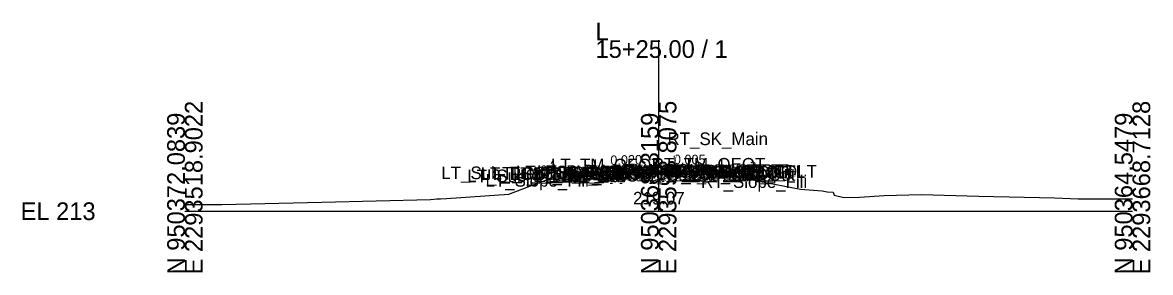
# Model space of a CAD drawing. Extents: x -26 to 7053, y -10 to 7035.
# Drawn here: x -25.7 to 152.8, y 6490.3 to 6529.9 of the extents above; entities that cross this region are included whole.
import ezdxf

# ---------------------------------------------------------------- set-up
doc = ezdxf.new("R2010")
doc.units = 0
for name, color, linetype in [('Default', 7, 'Continuous'), ('Exist Cross Section Cell', 7, 'Continuous'), ('Exist XS Center Line Elevation Label', 7, 'Continuous'), ('Exist XS Ground Line', 7, 'Continuous'), ('Prop CMT Pvmt Course 1', 7, 'Continuous'), ('Prop CMT Pvmt Course 2', 7, 'Continuous'), ('Prop CMT Pvmt Surface', 7, 'Continuous'), ('Prop CMT Pvmt Surface Overlay', 7, 'Continuous'), ('Prop CMT Pvmt Surface Shoulder', 7, 'Continuous'), ('Prop CMT Shld Paved Course 1', 7, 'Continuous'), ('Prop CMT Shld Paved Course 2', 7, 'Continuous'), ('Prop CMT Slope Grass', 7, 'Continuous'), ('Prop CMT Subgrade Earthwork', 7, 'Continuous'), ('Prop XS EOT Tick Mark', 7, 'Continuous'), ('Prop XS SE Text', 7, 'Continuous'), ('Prop XS Side Slope Text', 7, 'Continuous')]:
    doc.layers.add(name, color=color, linetype=linetype)

msp = doc.modelspace()

# ---------------------------------------------------------------- linework, layer by layer
at = {"layer": 'Exist Cross Section Cell'}
for p, q in [((75, 6500), (75, 6527.08)), ((0, 6500), (75, 6500)), ((75, 6500), (150, 6500))]:
    msp.add_line(p, q, dxfattribs=at)
at = {"layer": 'Exist XS Ground Line'}
for p, q in [((63.59, 6505.59), (66.19, 6505.83)), ((66.19, 6505.83), (68.01, 6505.89)), ((68.01, 6505.89), (74.91, 6506.07)), ((74.91, 6506.07), (80.13, 6505.93)), ((80.13, 6505.93), (83.17, 6505.86)), ((83.17, 6505.86), (85.02, 6505.7)), ((51.28, 6502.72), (56.42, 6504.65)), ((56.42, 6504.65), (57.47, 6505.04)), ((57.47, 6505.04), (63.59, 6505.59)), ((85.02, 6505.7), (87.85, 6505.45)), ((87.85, 6505.45), (90.85, 6504.76)), ((90.85, 6504.76), (97.44, 6503.49)), ((41.42, 6502.03), (51.28, 6502.72)), ((97.44, 6503.49), (100.87, 6503.21)), ((100.87, 6503.21), (101.69, 6503.07)), ((101.69, 6503.07), (102.61, 6503.02)), ((102.61, 6503.02), (102.8, 6502.54)), ((102.8, 6502.54), (104.29, 6502.15)), ((104.29, 6502.15), (106.81, 6502.24)), ((106.81, 6502.24), (110.69, 6502.49)), ((110.69, 6502.49), (116.57, 6502.63)), ((116.57, 6502.63), (125.67, 6502.41)), ((125.67, 6502.41), (137.64, 6502.11)), ((0, 6501.09), (0.37, 6501.08)), ((0.37, 6501.08), (1.81, 6501.09)), ((1.81, 6501.09), (5.83, 6501.05)), ((5.83, 6501.05), (21.68, 6501.42)), ((21.68, 6501.42), (38.87, 6501.87)), ((38.87, 6501.87), (39.9, 6501.97)), ((39.9, 6501.97), (40.48, 6501.96)), ((40.48, 6501.96), (41.42, 6502.03)), ((137.64, 6502.11), (141.39, 6501.97)), ((141.39, 6501.97), (150, 6501.95))]:
    msp.add_line(p, q, dxfattribs=at)
at = {"layer": 'Prop CMT Pvmt Course 1'}
for points in [[(75, 6506.47), (65, 6506.27)], [(65, 6506.27), (65, 6506.02)], [(65, 6506.02), (75, 6506.22)], [(75, 6506.35), (75, 6506.47)], [(75, 6506.47), (85, 6506.42)], [(75, 6506.35), (75, 6506.47)], [(75, 6506.22), (75, 6506.35), (75, 6506.35)], [(75, 6506.22), (75, 6506.35), (75, 6506.35)], [(85, 6506.17), (75, 6506.22)], [(85, 6506.42), (85, 6506.17)]]:
    msp.add_lwpolyline(points, dxfattribs=at)
at = {"layer": 'Prop CMT Pvmt Course 2'}
for points in [[(75, 6506.22), (65, 6506.02)], [(65, 6506.02), (65, 6505.69)], [(65, 6505.69), (75, 6505.89)], [(75, 6505.89), (75, 6506.22)], [(75, 6505.89), (75, 6506.22)], [(75, 6506.22), (85, 6506.17)], [(85, 6505.84), (75, 6505.89)], [(85, 6506.17), (85, 6505.84)]]:
    msp.add_lwpolyline(points, dxfattribs=at)
at = {"layer": 'Prop CMT Pvmt Surface'}
for points in [[(75, 6506.47), (65, 6506.27)], [(75, 6506.47), (85, 6506.42)]]:
    msp.add_lwpolyline(points, dxfattribs=at)
at = {"layer": 'Prop CMT Pvmt Surface Overlay'}
for points in [[(75, 6506.47), (65, 6506.27)], [(75, 6506.47), (85, 6506.42)]]:
    msp.add_lwpolyline(points, dxfattribs=at)
at = {"layer": 'Prop CMT Pvmt Surface Shoulder'}
for points in [[(65, 6506.27), (61.6, 6506.2)], [(85, 6506.42), (85.99, 6506.42)]]:
    msp.add_lwpolyline(points, dxfattribs=at)
at = {"layer": 'Prop CMT Shld Paved Course 1'}
for points in [[(65, 6506.27), (61.6, 6506.2), (61.34, 6505.95)], [(61.34, 6505.95), (65, 6506.02)], [(65, 6506.02), (65, 6506.27)], [(85, 6506.42), (85.99, 6506.42), (86.24, 6506.16)], [(85, 6506.17), (85, 6506.42)], [(86.24, 6506.16), (85, 6506.17)]]:
    msp.add_lwpolyline(points, dxfattribs=at)
at = {"layer": 'Prop CMT Shld Paved Course 2'}
for points in [[(65, 6506.02), (61.34, 6505.95), (60.84, 6505.94), (60.5, 6505.6)], [(65, 6505.69), (65, 6506.02)], [(85, 6506.17), (86.24, 6506.16), (86.74, 6506.16), (87.07, 6505.83)], [(85, 6505.84), (85, 6506.17)], [(87.07, 6505.83), (85, 6505.84)], [(60.5, 6505.6), (65, 6505.69)]]:
    msp.add_lwpolyline(points, dxfattribs=at)
at = {"layer": 'Prop CMT Slope Grass'}
for points in [[(59.33, 6506.02), (57.07, 6504.89)], [(61.6, 6506.2), (59.33, 6506.02)], [(85.99, 6506.42), (88.05, 6506.28)], [(88.05, 6506.28), (91.24, 6504.69)]]:
    msp.add_lwpolyline(points, dxfattribs=at)
at = {"layer": 'Prop CMT Subgrade Earthwork'}
for points in [[(60.5, 6505.6), (60.02, 6506.08)], [(75, 6505.89), (65, 6505.69)], [(75, 6505.89), (85, 6505.84)], [(85, 6505.84), (87.07, 6505.83)], [(87.07, 6505.83), (87.56, 6506.31)], [(65, 6505.69), (60.5, 6505.6)]]:
    msp.add_lwpolyline(points, dxfattribs=at)
at = {"layer": 'Prop XS EOT Tick Mark'}
for p, q in [((65, 6506.27), (65, 6508.18)), ((85, 6506.42), (85, 6508.33))]:
    msp.add_line(p, q, dxfattribs=at)

# ---------------------------------------------------------------- texts
at = {"layer": 'Default'}
for s, height, p in [('RT_SK_Main', 2, (76.4, 6510.47)), ('LT_TM_OEOT', 2, (57.94, 6506.31)), ('RT_TM_OEOT', 2, (73.9, 6506.43)), ('LT_Sub_Trench_Out_DLT', 2, (40.59, 6505.08)), ('LT_Sub_Trench_Out', 2, (44.7, 6504.6)), ('LT_PS2_Shelf_Out', 2, (46.82, 6504.94)), ('LT_Slope_Fill', 2, (47.59, 6503.89)), ('LT_GS_OS_CTL', 2, (48.7, 6505.02)), ('LT_PS2_OEOP', 2, (51.58, 6504.95)), ('LT_PS1_OEOP', 2, (52.4, 6505.2)), ('LT_Sub_OEOT', 2, (55.08, 6504.69)), ('LT_PV2_OEOT', 2, (55.17, 6505.02)), ('LT_PV1_OEOT', 2, (55.74, 6505.27)), ('RT_PV1_OEEOP_W', 2, (62.94, 6505.35)), ('LT_PV1_OEEOP_W', 2, (62.98, 6505.35)), ('RT_Sub_OEEOP', 2, (64.17, 6504.89)), ('LT_Sub_OEEOP', 2, (64.21, 6504.89)), ('RT_PV2_OEEOP', 2, (64.26, 6505.22)), ('LT_PV2_OEEOP', 2, (64.31, 6505.22)), ('PV1_PGL_W', 2, (67.58, 6505.35)), ('RT_Sub_Trench_Out_DLT', 2, (68.08, 6505.31)), ('PV1_PGL', 2, (69.47, 6505.47)), ('RT_Sub_Trench_Out', 2, (71.23, 6504.83)), ('RT_PS2_Shelf_Out', 2, (72.68, 6505.16)), ('RT_Sub_OEOT', 2, (75.03, 6504.84)), ('RT_PV2_OEOT', 2, (75.13, 6505.17)), ('RT_PV1_OEOT', 2, (75.69, 6505.42)), ('RT_PS2_OEOP', 2, (76.43, 6505.16)), ('RT_PS1_OEOP', 2, (76.74, 6505.42)), ('RT_GS_OS_CTL', 2, (77.37, 6505.28)), ('RT_Slope_Fill', 2, (81.71, 6503.69)), ('-', 0.0001, (0, 6500))]:
    msp.add_text(s, height=height, dxfattribs=at).set_placement(p)
at = {"layer": 'Exist Cross Section Cell'}
for s, p in [('L', (65, 6527.08)), ('15+25.00 / 1', (65, 6524.28)), ('EL 213', (-26, 6498.6))]:
    msp.add_text(s, height=2.8, dxfattribs=at).set_placement(p)
for s, p in [('E 2293518.9022', (2.8, 6490)), ('E 2293593.8075', (77.8, 6490)), ('E 2293668.7128', (152.8, 6490)), ('N 950372.0839', (0, 6490)), ('N 950368.3159', (75, 6490)), ('N 950364.5479', (150, 6490))]:
    msp.add_text(s, height=2.8, rotation=90, dxfattribs=at).set_placement(p)
at = {"layer": 'Exist XS Center Line Elevation Label'}
msp.add_text('219.07', height=2, dxfattribs=at).set_placement((70.94, 6501.07))
at = {"layer": 'Prop XS SE Text'}
for s, rotation, p in [('0.020', 1.1458, (67.36, 6507.32)), ('0.005', 359.7135, (77.4, 6507.46))]:
    msp.add_text(s, height=1.5, rotation=rotation, dxfattribs=at).set_placement(p)
at = {"layer": 'Prop XS Side Slope Text'}
for rotation, p in [(26.5651, (56.8, 6505.6)), (333.4349, (88.92, 6506.69))]:
    msp.add_text('2:1', height=1.5, rotation=rotation, dxfattribs=at).set_placement(p)

doc.saveas('drawing.dxf')
